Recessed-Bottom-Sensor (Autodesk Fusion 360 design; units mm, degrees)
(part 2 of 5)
sketch "M5 stop reinforcement bolt" plane through (-36.1, 0, 0) normal (1, 0, 0) x axis (0, 0, -1)
  circle C1 centre (-79.6754, -33.9652) radius 2.7
extrude "Extrude12" cut sketch "M5 stop reinforcement bolt" along normal blind 27.2
work_plane "WorkPlane13" AlongDistance -15.4 ExtraOffset 0
sketch "M5 captive stop nut" plane through (-15.4, 0, 0) normal (1, 0, 0) x axis (0, 0, -1)
  line L1 (-83.8754, -31.5403) -> (-79.6754, -29.1154)
  line L2 (-83.8754, -36.39) -> (-83.8754, -31.5403)
  line L3 (-79.6754, -38.8149) -> (-83.8754, -36.39)
  line L4 (-75.4754, -36.39) -> (-79.6754, -38.8149)
  line L5 (-75.4754, -31.5403) -> (-75.4754, -36.39)
  line L6 (-79.6754, -29.1154) -> (-75.4754, -31.5403)
extrude "Extrude13" cut sketch "M5 captive stop nut" along normal blind 6.5
work_plane "WorkPlane14" AlongDistance -36 ExtraOffset 0
sketch "Broad stop support ear (1)" plane through (-36, 0, 0) normal (1, 0, 0) x axis (0, 0, -1)
  line L1 (-60, 44) -> (-60, 20)
  line L2 (-90, 44) -> (-60, 44)
  line L3 (-90, 20) -> (-90, 44)
  line L4 (-60, 20) -> (-90, 20)
extrude "Extrude14" add sketch "Broad stop support ear (1)" along normal blind 12
work_plane "WorkPlane15" AlongDistance -24 ExtraOffset 0
sketch "Integrated steel-core end stop (1)" plane through (-24, 0, 0) normal (1, 0, 0) x axis (0, 0, -1)
  circle C1 centre (-79.6754, 33.9652) radius 6
extrude "Extrude15" add sketch "Integrated steel-core end stop (1)" along normal blind 15
work_plane "WorkPlane16" AlongDistance -36.1 ExtraOffset 0
sketch "M5 stop reinforcement bolt (1)" plane through (-36.1, 0, 0) normal (1, 0, 0) x axis (0, 0, -1)
  circle C1 centre (-79.6754, 33.9652) radius 2.7
extrude "Extrude16" cut sketch "M5 stop reinforcement bolt (1)" along normal blind 27.2
work_plane "WorkPlane17" AlongDistance -15.4 ExtraOffset 0
sketch "M5 captive stop nut (1)" plane through (-15.4, 0, 0) normal (1, 0, 0) x axis (0, 0, -1)
  line L1 (-83.8754, 36.39) -> (-79.6754, 38.8149)
  line L2 (-83.8754, 31.5403) -> (-83.8754, 36.39)
  line L3 (-79.6754, 29.1154) -> (-83.8754, 31.5403)
  line L4 (-75.4754, 31.5403) -> (-79.6754, 29.1154)
  line L5 (-75.4754, 36.39) -> (-75.4754, 31.5403)
  line L6 (-79.6754, 38.8149) -> (-75.4754, 36.39)
extrude "Extrude17" cut sketch "M5 captive stop nut (1)" along normal blind 6.5
work_plane "WorkPlane13" AlongDistance -24 ExtraOffset 0
sketch "Restore shaft socket through stop-lug root" plane through (-24, 0, 0) normal (1, 0, 0) x axis (0, 0, -1)
  line L1 (-69.6247, 6.65) -> (-60.3753, 6.65)
  arc A1 centre (-65, 0) radius 8.1 clockwise from (-60.3753, 6.65) to (-69.6247, 6.65)
extrude "Extrude13" cut sketch "Restore shaft socket through stop-lug root" along normal blind 48
work_plane "WorkPlane10" AlongDistance -24.1 ExtraOffset 0
sketch "Cam sweep clearance through crossblock" plane through (-24.1, 0, 0) normal (1, 0, 0) x axis (0, 0, -1)
  circle C1 centre (-65, 0) radius 51
extrude "Extrude10" cut sketch "Cam sweep clearance through crossblock" along normal blind 48.2
work_plane "WorkPlane10" AlongDistance 36 ExtraOffset 0
sketch "Rigid sensor carriage support" plane through (36, 0, 0) normal (1, 0, 0) x axis (0, 0, -1)
  line L1 (-49, -18) -> (-49, -28)
  line L2 (-81, -18) -> (-49, -18)
  line L3 (-81, -28) -> (-81, -18)
  line L4 (-49, -28) -> (-81, -28)
extrude "Extrude10" add sketch "Rigid sensor carriage support" along normal blind 44
work_plane "WorkPlane11" AlongDistance -28.1 ExtraOffset 0
sketch "M3 sensor carriage heat set" plane through (0, -28.1, 0) normal (0, 1, 0) x axis (1, 0, 0)
  circle C1 centre (74, -65) radius 2
extrude "Extrude11" cut sketch "M3 sensor carriage heat set" along normal blind 6.8
work_plane "WorkPlane12" AlongDistance 36 ExtraOffset 0
sketch "Rigid sensor carriage support (1)" plane through (36, 0, 0) normal (1, 0, 0) x axis (0, 0, -1)
  line L1 (-49, 28) -> (-49, 18)
  line L2 (-81, 28) -> (-49, 28)
  line L3 (-81, 18) -> (-81, 28)
  line L4 (-49, 18) -> (-81, 18)
extrude "Extrude12" add sketch "Rigid sensor carriage support (1)" along normal blind 44
work_plane "WorkPlane13" AlongDistance 21.3 ExtraOffset 0
sketch "M3 sensor carriage heat set (1)" plane through (0, 21.3, 0) normal (0, 1, 0) x axis (1, 0, 0)
  circle C1 centre (74, -65) radius 2
extrude "Extrude13" cut sketch "M3 sensor carriage heat set (1)" along normal blind 6.8
work_plane "WorkPlane1" AlongDistance -24 ExtraOffset 0
sketch "Controlled follower end float" plane through (-24, 0, 0) normal (1, 0, 0) x axis (0, 0, -1)
  circle C1 centre (-12, -35) radius 6
extrude "Extrude1" new body sketch "Controlled follower end float" along normal blind 27.8 bodies "P21 Follower left axial spacer"
work_plane "WorkPlane2" AlongDistance -24.1 ExtraOffset 0
sketch "Pivot sleeve running clearance" plane through (-24.1, 0, 0) normal (1, 0, 0) x axis (0, 0, -1)
  circle C1 centre (-12, -35) radius 4.2
extrude "Extrude2" cut sketch "Pivot sleeve running clearance" along normal blind 28
work_plane "WorkPlane1" AlongDistance 20.2 ExtraOffset 0
sketch "Controlled follower end float" plane through (20.2, 0, 0) normal (1, 0, 0) x axis (0, 0, -1)
  circle C1 centre (-12, -35) radius 6
extrude "Extrude1" new body sketch "Controlled follower end float" along normal blind 3.8 bodies "P22 Follower right axial spacer"
work_plane "WorkPlane2" AlongDistance 20.1 ExtraOffset 0
sketch "Pivot sleeve running clearance" plane through (20.1, 0, 0) normal (1, 0, 0) x axis (0, 0, -1)
  circle C1 centre (-12, -35) radius 4.2
extrude "Extrude2" cut sketch "Pivot sleeve running clearance" along normal blind 4
work_plane "WorkPlane1" AlongDistance 3.1 ExtraOffset 0
sketch "Roller axle M3 nut" plane through (3.1, 0, 0) normal (1, 0, 0) x axis (0, 0, -1)
  line L1 (-14.75, 1.5877) -> (-12, 3.1754)
  line L2 (-14.75, -1.5877) -> (-14.75, 1.5877)
  line L3 (-12, -3.1754) -> (-14.75, -1.5877)
  line L4 (-9.25, -1.5877) -> (-12, -3.1754)
  line L5 (-9.25, 1.5877) -> (-9.25, -1.5877)
  line L6 (-12, 3.1754) -> (-9.25, 1.5877)
extrude "Extrude1" new body sketch "Roller axle M3 nut" along normal blind 2.4 bodies "HARDWARE Roller axle M3 nut"
work_plane "WorkPlane2" AlongDistance 3 ExtraOffset 0
sketch "Thread envelope" plane through (3, 0, 0) normal (1, 0, 0) x axis (0, 0, -1)
  circle C1 centre (-12, 0) radius 1.5
extrude "Extrude2" cut sketch "Thread envelope" along normal blind 2.6
work_plane "WorkPlane14" AlongDistance 23.9 ExtraOffset 0
sketch "Cam lateral service opening" plane through (23.9, 0, 0) normal (1, 0, 0) x axis (0, 0, -1)
  line L1 (-42.2047, 46.7373) -> (-43.8497, 47.5044)
  line L2 (-40.5875, 45.9133) -> (-42.2047, 46.7373)
  line L3 (-39, 45.0333) -> (-40.5875, 45.9133)
  line L4 (-37.4442, 44.0985) -> (-39, 45.0333)
  line L5 (-35.922, 43.11) -> (-37.4442, 44.0985)
  line L6 (-34.4352, 42.0689) -> (-35.922, 43.11)
  line L7 (-32.9856, 40.9766) -> (-34.4352, 42.0689)
  line L8 (-31.575, 39.8343) -> (-32.9856, 40.9766)
  line L9 (-30.2052, 38.6435) -> (-31.575, 39.8343)
  line L10 (-28.8778, 37.4057) -> (-30.2052, 38.6435)
  line L11 (-27.5943, 36.1222) -> (-28.8778, 37.4057)
  line L12 (-26.3565, 34.7948) -> (-27.5943, 36.1222)
  line L13 (-25.1657, 33.425) -> (-26.3565, 34.7948)
  line L14 (-24.0234, 32.0144) -> (-25.1657, 33.425)
  line L15 (-22.9311, 30.5648) -> (-24.0234, 32.0144)
  line L16 (-21.89, 29.078) -> (-22.9311, 30.5648)
  line L17 (-20.9015, 27.5558) -> (-21.89, 29.078)
  line L18 (-19.9667, 26) -> (-20.9015, 27.5558)
  line L19 (-19.0867, 24.4125) -> (-19.9667, 26)
  line L20 (-18.2627, 22.7953) -> (-19.0867, 24.4125)
  line L21 (-17.4956, 21.1503) -> (-18.2627, 22.7953)
  line L22 (-16.7864, 19.4795) -> (-17.4956, 21.1503)
  line L23 (-16.136, 17.785) -> (-16.7864, 19.4795)
  line L24 (-15.5451, 16.0689) -> (-16.136, 17.785)
  line L25 (-15.0144, 14.3331) -> (-15.5451, 16.0689)
  line L26 (-14.5446, 12.5799) -> (-15.0144, 14.3331)
  line L27 (-14.1363, 10.8114) -> (-14.5446, 12.5799)
  line L28 (-13.79, 9.0297) -> (-14.1363, 10.8114)
  line L29 (-13.5061, 7.237) -> (-13.79, 9.0297)
  line L30 (-13.2849, 5.4355) -> (-13.5061, 7.237)
  line L31 (-13.1267, 3.6273) -> (-13.2849, 5.4355)
  line L32 (-13.0317, 1.8148) -> (-13.1267, 3.6273)
  line L33 (-13, 0) -> (-13.0317, 1.8148)
  line L34 (-13.0317, -1.8148) -> (-13, 0)
  line L35 (-13.1267, -3.6273) -> (-13.0317, -1.8148)
  line L36 (-13.2849, -5.4355) -> (-13.1267, -3.6273)
  line L37 (-13.5061, -7.237) -> (-13.2849, -5.4355)
  line L38 (-13.79, -9.0297) -> (-13.5061, -7.237)
  line L39 (-14.1363, -10.8114) -> (-13.79, -9.0297)
  line L40 (-14.5446, -12.5799) -> (-14.1363, -10.8114)
  line L41 (-15.0144, -14.3331) -> (-14.5446, -12.5799)
  line L42 (-15.5451, -16.0689) -> (-15.0144, -14.3331)
  line L43 (-16.136, -17.785) -> (-15.5451, -16.0689)
  line L44 (-16.7864, -19.4795) -> (-16.136, -17.785)
  line L45 (-17.4956, -21.1503) -> (-16.7864, -19.4795)
  line L46 (-18.2627, -22.7953) -> (-17.4956, -21.1503)
  line L47 (-19.0867, -24.4125) -> (-18.2627, -22.7953)
  line L48 (-19.9667, -26) -> (-19.0867, -24.4125)
  line L49 (-20.9015, -27.5558) -> (-19.9667, -26)
  line L50 (-21.89, -29.078) -> (-20.9015, -27.5558)
  line L51 (-22.9311, -30.5648) -> (-21.89, -29.078)
  line L52 (-24.0234, -32.0144) -> (-22.9311, -30.5648)
  line L53 (-25.1657, -33.425) -> (-24.0234, -32.0144)
  line L54 (-26.3565, -34.7948) -> (-25.1657, -33.425)
  line L55 (-27.5943, -36.1222) -> (-26.3565, -34.7948)
  line L56 (-28.8778, -37.4057) -> (-27.5943, -36.1222)
  line L57 (-30.2052, -38.6435) -> (-28.8778, -37.4057)
  line L58 (-31.575, -39.8343) -> (-30.2052, -38.6435)
  line L59 (-32.9856, -40.9766) -> (-31.575, -39.8343)
  line L60 (-34.4352, -42.0689) -> (-32.9856, -40.9766)
  line L61 (-35.922, -43.11) -> (-34.4352, -42.0689)
  line L62 (-37.4442, -44.0985) -> (-35.922, -43.11)
  line L63 (-39, -45.0333) -> (-37.4442, -44.0985)
  line L64 (-40.5875, -45.9133) -> (-39, -45.0333)
  line L65 (-42.2047, -46.7373) -> (-40.5875, -45.9133)
  line L66 (-43.8497, -47.5044) -> (-42.2047, -46.7373)
  line L67 (-54.4248, -23.7522) -> (-43.8497, -47.5044)
  line L68 (-53.6024, -23.3686) -> (-54.4248, -23.7522)
  line L69 (-52.7937, -22.9566) -> (-53.6024, -23.3686)
  line L70 (-52, -22.5167) -> (-52.7937, -22.9566)
  line L71 (-51.2221, -22.0493) -> (-52, -22.5167)
  line L72 (-50.461, -21.555) -> (-51.2221, -22.0493)
  line L73 (-49.7176, -21.0344) -> (-50.461, -21.555)
  line L74 (-48.9928, -20.4883) -> (-49.7176, -21.0344)
  line L75 (-48.2875, -19.9172) -> (-48.9928, -20.4883)
  line L76 (-47.6026, -19.3218) -> (-48.2875, -19.9172)
  line L77 (-46.9389, -18.7028) -> (-47.6026, -19.3218)
  line L78 (-46.2972, -18.0611) -> (-46.9389, -18.7028)
  line L79 (-45.6782, -17.3974) -> (-46.2972, -18.0611)
  line L80 (-45.0828, -16.7125) -> (-45.6782, -17.3974)
  line L81 (-44.5117, -16.0072) -> (-45.0828, -16.7125)
  line L82 (-43.9656, -15.2824) -> (-44.5117, -16.0072)
  line L83 (-43.445, -14.539) -> (-43.9656, -15.2824)
  line L84 (-42.9507, -13.7779) -> (-43.445, -14.539)
  line L85 (-42.4833, -13) -> (-42.9507, -13.7779)
  line L86 (-42.0434, -12.2063) -> (-42.4833, -13)
  line L87 (-41.6314, -11.3976) -> (-42.0434, -12.2063)
  line L88 (-41.2478, -10.5752) -> (-41.6314, -11.3976)
  line L89 (-40.8932, -9.7398) -> (-41.2478, -10.5752)
  line L90 (-40.568, -8.8925) -> (-40.8932, -9.7398)
  line L91 (-40.2725, -8.0344) -> (-40.568, -8.8925)
  line L92 (-40.0072, -7.1666) -> (-40.2725, -8.0344)
  line L93 (-39.7723, -6.29) -> (-40.0072, -7.1666)
  line L94 (-39.5682, -5.4057) -> (-39.7723, -6.29)
  line L95 (-39.395, -4.5149) -> (-39.5682, -5.4057)
  line L96 (-39.253, -3.6185) -> (-39.395, -4.5149)
  line L97 (-39.1424, -2.7177) -> (-39.253, -3.6185)
  line L98 (-39.0633, -1.8137) -> (-39.1424, -2.7177)
  line L99 (-39.0158, -0.9074) -> (-39.0633, -1.8137)
  line L100 (-39, 0) -> (-39.0158, -0.9074)
  line L101 (-39.0158, 0.9074) -> (-39, 0)
  line L102 (-39.0633, 1.8137) -> (-39.0158, 0.9074)
  line L103 (-39.1424, 2.7177) -> (-39.0633, 1.8137)
  line L104 (-39.253, 3.6185) -> (-39.1424, 2.7177)
  line L105 (-39.395, 4.5149) -> (-39.253, 3.6185)
  line L106 (-39.5682, 5.4057) -> (-39.395, 4.5149)
  line L107 (-39.7723, 6.29) -> (-39.5682, 5.4057)
  line L108 (-40.0072, 7.1666) -> (-39.7723, 6.29)
  line L109 (-40.2725, 8.0344) -> (-40.0072, 7.1666)
  line L110 (-40.568, 8.8925) -> (-40.2725, 8.0344)
  line L111 (-40.8932, 9.7398) -> (-40.568, 8.8925)
  line L112 (-41.2478, 10.5752) -> (-40.8932, 9.7398)
  line L113 (-41.6314, 11.3976) -> (-41.2478, 10.5752)
  line L114 (-42.0434, 12.2063) -> (-41.6314, 11.3976)
  line L115 (-42.4833, 13) -> (-42.0434, 12.2063)
  line L116 (-42.9507, 13.7779) -> (-42.4833, 13)
  line L117 (-43.445, 14.539) -> (-42.9507, 13.7779)
  line L118 (-43.9656, 15.2824) -> (-43.445, 14.539)
  line L119 (-44.5117, 16.0072) -> (-43.9656, 15.2824)
  line L120 (-45.0828, 16.7125) -> (-44.5117, 16.0072)
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extrude "Extrude14" cut sketch "Cam lateral service opening" along normal blind 12.2
work_plane "WorkPlane15" AlongDistance 36 ExtraOffset 0
sketch "Clear service path beneath sensor rails" plane through (36, 0, 0) normal (1, 0, 0) x axis (0, 0, -1)
  line L1 (-48.9, -18) -> (-48.9, -28)
  line L2 (-56, -18) -> (-48.9, -18)
  line L3 (-56, -28) -> (-56, -18)
  line L4 (-48.9, -28) -> (-56, -28)
extrude "Extrude15" cut sketch "Clear service path beneath sensor rails" along normal blind 44.1
work_plane "WorkPlane16" AlongDistance 36 ExtraOffset 0
sketch "Clear service path beneath sensor rails (1)" plane through (36, 0, 0) normal (1, 0, 0) x axis (0, 0, -1)
  line L1 (-48.9, 28) -> (-48.9, 18)
  line L2 (-56, 28) -> (-48.9, 28)
  line L3 (-56, 18) -> (-56, 28)
  line L4 (-48.9, 18) -> (-56, 18)
extrude "Extrude16" cut sketch "Clear service path beneath sensor rails (1)" along normal blind 44.1
work_plane "WorkPlane11" AlongDistance -24 ExtraOffset 0
sketch "Raise mount clear of rail bolt axes" plane through (-24, 0, 0) normal (1, 0, 0) x axis (0, 0, -1)
  line L1 (-52, -44) -> (-52, -66)
  line L2 (-57, -44) -> (-52, -44)
  line L3 (-57, -66) -> (-57, -44)
  line L4 (-52, -66) -> (-57, -66)
extrude "Extrude11" add sketch "Raise mount clear of rail bolt axes" along normal blind 48
work_plane "WorkPlane12" AlongDistance -24 ExtraOffset 0
sketch "Close old block mounting hole" plane through (-24, 0, 0) normal (1, 0, 0) x axis (0, 0, -1)
  circle C1 centre (-44, -59) radius 2.01
extrude "Extrude12" add sketch "Close old block mounting hole" along normal blind 8.7
work_plane "WorkPlane13" AlongDistance -24.1 ExtraOffset 0
sketch "Raised M3 block insert" plane through (-24.1, 0, 0) normal (1, 0, 0) x axis (0, 0, -1)
  circle C1 centre (-52, -59) radius 2
extrude "Extrude13" cut sketch "Raised M3 block insert" along normal blind 8.9
work_plane "WorkPlane14" AlongDistance 15.3 ExtraOffset 0
sketch "Close old block mounting hole (1)" plane through (15.3, 0, 0) normal (1, 0, 0) x axis (0, 0, -1)
  circle C1 centre (-44, -59) radius 2.01
extrude "Extrude14" add sketch "Close old block mounting hole (1)" along normal blind 8.7
work_plane "WorkPlane15" AlongDistance 15.2 ExtraOffset 0
sketch "Raised M3 block insert (1)" plane through (15.2, 0, 0) normal (1, 0, 0) x axis (0, 0, -1)
  circle C1 centre (-52, -59) radius 2
extrude "Extrude15" cut sketch "Raised M3 block insert (1)" along normal blind 8.9
work_plane "WorkPlane18" AlongDistance -36 ExtraOffset 0
sketch "Close old plate mounting hole" plane through (-36, 0, 0) normal (1, 0, 0) x axis (0, 0, -1)
  circle C1 centre (-44, -59) radius 1.71
extrude "Extrude18" add sketch "Close old plate mounting hole" along normal blind 12
work_plane "WorkPlane19" AlongDistance -36.1 ExtraOffset 0
sketch "Raised M3 block fastener" plane through (-36.1, 0, 0) normal (1, 0, 0) x axis (0, 0, -1)
  circle C1 centre (-52, -59) radius 1.7
extrude "Extrude19" cut sketch "Raised M3 block fastener" along normal blind 12.2
work_plane "WorkPlane17" AlongDistance 24 ExtraOffset 0
sketch "Close old plate mounting hole" plane through (24, 0, 0) normal (1, 0, 0) x axis (0, 0, -1)
  circle C1 centre (-44, -59) radius 1.71
extrude "Extrude17" add sketch "Close old plate mounting hole" along normal blind 12
work_plane "WorkPlane18" AlongDistance 23.9 ExtraOffset 0
sketch "Raised M3 block fastener" plane through (23.9, 0, 0) normal (1, 0, 0) x axis (0, 0, -1)
  circle C1 centre (-52, -59) radius 1.7
extrude "Extrude18" cut sketch "Raised M3 block fastener" along normal blind 12.2
work_plane "WorkPlane16" AlongDistance -24 ExtraOffset 0
sketch "Close old block mounting hole (2)" plane through (-24, 0, 0) normal (1, 0, 0) x axis (0, 0, -1)
  circle C1 centre (-44, -51) radius 2.01
extrude "Extrude16" add sketch "Close old block mounting hole (2)" along normal blind 8.7
work_plane "WorkPlane17" AlongDistance -24.1 ExtraOffset 0
sketch "Raised M3 block insert (2)" plane through (-24.1, 0, 0) normal (1, 0, 0) x axis (0, 0, -1)
  circle C1 centre (-52, -51) radius 2
extrude "Extrude17" cut sketch "Raised M3 block insert (2)" along normal blind 8.9
work_plane "WorkPlane18" AlongDistance 15.3 ExtraOffset 0
sketch "Close old block mounting hole (3)" plane through (15.3, 0, 0) normal (1, 0, 0) x axis (0, 0, -1)
  circle C1 centre (-44, -51) radius 2.01
extrude "Extrude18" add sketch "Close old block mounting hole (3)" along normal blind 8.7
work_plane "WorkPlane19" AlongDistance 15.2 ExtraOffset 0
sketch "Raised M3 block insert (3)" plane through (15.2, 0, 0) normal (1, 0, 0) x axis (0, 0, -1)
  circle C1 centre (-52, -51) radius 2
extrude "Extrude19" cut sketch "Raised M3 block insert (3)" along normal blind 8.9
work_plane "WorkPlane20" AlongDistance -36 ExtraOffset 0
sketch "Close old plate mounting hole (1)" plane through (-36, 0, 0) normal (1, 0, 0) x axis (0, 0, -1)
  circle C1 centre (-44, -51) radius 1.71
extrude "Extrude20" add sketch "Close old plate mounting hole (1)" along normal blind 12
work_plane "WorkPlane21" AlongDistance -36.1 ExtraOffset 0
sketch "Raised M3 block fastener (1)" plane through (-36.1, 0, 0) normal (1, 0, 0) x axis (0, 0, -1)
  circle C1 centre (-52, -51) radius 1.7
extrude "Extrude21" cut sketch "Raised M3 block fastener (1)" along normal blind 12.2
work_plane "WorkPlane19" AlongDistance 24 ExtraOffset 0
sketch "Close old plate mounting hole (1)" plane through (24, 0, 0) normal (1, 0, 0) x axis (0, 0, -1)
  circle C1 centre (-44, -51) radius 1.71
extrude "Extrude19" add sketch "Close old plate mounting hole (1)" along normal blind 12
work_plane "WorkPlane20" AlongDistance 23.9 ExtraOffset 0
sketch "Raised M3 block fastener (1)" plane through (23.9, 0, 0) normal (1, 0, 0) x axis (0, 0, -1)
  circle C1 centre (-52, -51) radius 1.7
extrude "Extrude20" cut sketch "Raised M3 block fastener (1)" along normal blind 12.2
work_plane "WorkPlane20" AlongDistance 51.9 ExtraOffset 0
sketch "Continue adjuster bore" plane through (0, 0, 51.9) normal (0, 0, 1) x axis (1, 0, 0)
  circle C1 centre (12, -55) radius 2.2
extrude "Extrude20" cut sketch "Continue adjuster bore" along normal blind 5.2
work_plane "WorkPlane21" AlongDistance 51.9 ExtraOffset 0
sketch "Continue guide bore" plane through (0, 0, 51.9) normal (0, 0, 1) x axis (1, 0, 0)
  circle C1 centre (5, -55) radius 1.7
extrude "Extrude21" cut sketch "Continue guide bore" along normal blind 5.2
work_plane "WorkPlane22" AlongDistance 51.9 ExtraOffset 0
sketch "Continue guide bore (1)" plane through (0, 0, 51.9) normal (0, 0, 1) x axis (1, 0, 0)
  circle C1 centre (19, -55) radius 1.7
extrude "Extrude22" cut sketch "Continue guide bore (1)" along normal blind 5.2
work_plane "WorkPlane23" AlongDistance -24.1 ExtraOffset 0
sketch "Preserve cam sweep clearance" plane through (-24.1, 0, 0) normal (1, 0, 0) x axis (0, 0, -1)
  circle C1 centre (-65, 0) radius 51
extrude "Extrude23" cut sketch "Preserve cam sweep clearance" along normal blind 48.2
work_plane "WorkPlane1" AlongDistance -23.85 ExtraOffset 0
sketch "Controlled rotor axial clearance" plane through (-23.85, 0, 0) normal (1, 0, 0) x axis (0, 0, -1)
  circle C1 centre (-65, 0) radius 10
extrude "Extrude1" new body sketch "Controlled rotor axial clearance" along normal blind 16.85 bodies "P23 Left rotor thrust spacer"
work_plane "WorkPlane2" AlongDistance -23.95 ExtraOffset 0
sketch "Free spacer bore" plane through (-23.95, 0, 0) normal (1, 0, 0) x axis (0, 0, -1)
  circle C1 centre (-65, 0) radius 8.2
extrude "Extrude2" cut sketch "Free spacer bore" along normal blind 17.05
work_plane "WorkPlane1" AlongDistance 7 ExtraOffset 0
sketch "Controlled rotor axial clearance" plane through (7, 0, 0) normal (1, 0, 0) x axis (0, 0, -1)
  circle C1 centre (-65, 0) radius 10
extrude "Extrude1" new body sketch "Controlled rotor axial clearance" along normal blind 16.85 bodies "P24 Right rotor thrust spacer"
work_plane "WorkPlane2" AlongDistance 6.9 ExtraOffset 0
sketch "Free spacer bore" plane through (6.9, 0, 0) normal (1, 0, 0) x axis (0, 0, -1)
  circle C1 centre (-65, 0) radius 8.2
extrude "Extrude2" cut sketch "Free spacer bore" along normal blind 17.05
work_plane "WorkPlane22" AlongDistance -76 ExtraOffset 0
sketch "Restore rail bolt clearance after hole filling" plane through (0, -76, 0) normal (0, 1, 0) x axis (1, 0, 0)
  circle C1 centre (-30, -45) radius 2.7
extrude "Extrude22" cut sketch "Restore rail bolt clearance after hole filling" along normal blind 22
work_plane "WorkPlane23" AlongDistance 54 ExtraOffset 0
sketch "Restore rail bolt clearance after hole filling (1)" plane through (0, 54, 0) normal (0, 1, 0) x axis (1, 0, 0)
  circle C1 centre (-30, -45) radius 2.7
work_plane "WorkPlane24" AlongDistance -55 ExtraOffset 0
sketch "Restore rail head access after hole filling" plane through (0, -55, 0) normal (0, 1, 0) x axis (1, 0, 0)
  circle C1 centre (-30, -45) radius 5.3
extrude "Extrude24" cut sketch "Restore rail head access after hole filling" along normal blind 12
work_plane "WorkPlane25" AlongDistance 43 ExtraOffset 0
sketch "Restore rail head access after hole filling (1)" plane through (0, 43, 0) normal (0, 1, 0) x axis (1, 0, 0)
  circle C1 centre (-30, -45) radius 5.3
work_plane "WorkPlane21" AlongDistance -76 ExtraOffset 0
sketch "Restore rail bolt clearance after hole filling" plane through (0, -76, 0) normal (0, 1, 0) x axis (1, 0, 0)
  circle C1 centre (30, -45) radius 2.7
extrude "Extrude21" cut sketch "Restore rail bolt clearance after hole filling" along normal blind 22
work_plane "WorkPlane22" AlongDistance 54 ExtraOffset 0
sketch "Restore rail bolt clearance after hole filling (1)" plane through (0, 54, 0) normal (0, 1, 0) x axis (1, 0, 0)
  circle C1 centre (30, -45) radius 2.7
work_plane "WorkPlane23" AlongDistance -55 ExtraOffset 0
sketch "Restore rail head access after hole filling" plane through (0, -55, 0) normal (0, 1, 0) x axis (1, 0, 0)
  circle C1 centre (30, -45) radius 5.3
extrude "Extrude23" cut sketch "Restore rail head access after hole filling" along normal blind 12
work_plane "WorkPlane24" AlongDistance 43 ExtraOffset 0
sketch "Restore rail head access after hole filling (1)" plane through (0, 43, 0) normal (0, 1, 0) x axis (1, 0, 0)
  circle C1 centre (30, -45) radius 5.3
work_plane "WorkPlane14" AlongDistance -18.1 ExtraOffset 0
sketch "Stop lug clearance for concentric thrust spacer" plane through (-18.1, 0, 0) normal (1, 0, 0) x axis (0, 0, -1)
  circle C1 centre (-65, 0) radius 10.2
extrude "Extrude14" cut sketch "Stop lug clearance for concentric thrust spacer" along normal blind 11
work_plane "WorkPlane15" AlongDistance -18.1 ExtraOffset 0
sketch "Complete stop lug relief to rotor face" plane through (-18.1, 0, 0) normal (1, 0, 0) x axis (0, 0, -1)
  circle C1 centre (-65, 0) radius 10.2
extrude "Extrude15" cut sketch "Complete stop lug relief to rotor face" along normal blind 11.1
ground "Pin2"
ground "Pin3"
ground "Pin4"
ground "Pin5"
ground "Pin6"
ground "Pin11"
ground "Pin12"
ground "Pin48"
ground "Pin49"
work_plane "WorkPlane24" AlongDistance -24 ExtraOffset 0
sketch "Extra roof over relocated heat-set inserts" plane through (-24, 0, 0) normal (1, 0, 0) x axis (0, 0, -1)
  line L1 (-57, -44) -> (-57, -66)
  line L2 (-59, -44) -> (-57, -44)
  line L3 (-59, -66) -> (-59, -44)
  line L4 (-57, -66) -> (-59, -66)
extrude "Extrude24" add sketch "Extra roof over relocated heat-set inserts" along normal blind 48
work_plane "WorkPlane25" AlongDistance -24 ExtraOffset 0
sketch "Fill former insert location" plane through (-24, 0, 0) normal (1, 0, 0) x axis (0, 0, -1)
  circle C1 centre (-52, -59) radius 2.01
extrude "Extrude25" add sketch "Fill former insert location" along normal blind 8.7
work_plane "WorkPlane26" AlongDistance 15.3 ExtraOffset 0
sketch "Fill former insert location (1)" plane through (15.3, 0, 0) normal (1, 0, 0) x axis (0, 0, -1)
  circle C1 centre (-52, -59) radius 2.01
extrude "Extrude26" add sketch "Fill former insert location (1)" along normal blind 8.7
work_plane "WorkPlane26" AlongDistance -36 ExtraOffset 0
sketch "Fill former plate mounting hole" plane through (-36, 0, 0) normal (1, 0, 0) x axis (0, 0, -1)
  circle C1 centre (-52, -59) radius 1.71
extrude "Extrude26" add sketch "Fill former plate mounting hole" along normal blind 12
work_plane "WorkPlane25" AlongDistance 24 ExtraOffset 0
sketch "Fill former plate mounting hole" plane through (24, 0, 0) normal (1, 0, 0) x axis (0, 0, -1)
  circle C1 centre (-52, -59) radius 1.71
extrude "Extrude25" add sketch "Fill former plate mounting hole" along normal blind 12
work_plane "WorkPlane27" AlongDistance -24 ExtraOffset 0
sketch "Fill former insert location (2)" plane through (-24, 0, 0) normal (1, 0, 0) x axis (0, 0, -1)
  circle C1 centre (-52, -51) radius 2.01
extrude "Extrude27" add sketch "Fill former insert location (2)" along normal blind 8.7
work_plane "WorkPlane28" AlongDistance 15.3 ExtraOffset 0
sketch "Fill former insert location (3)" plane through (15.3, 0, 0) normal (1, 0, 0) x axis (0, 0, -1)
  circle C1 centre (-52, -51) radius 2.01
extrude "Extrude28" add sketch "Fill former insert location (3)" along normal blind 8.7
work_plane "WorkPlane27" AlongDistance -36 ExtraOffset 0
sketch "Fill former plate mounting hole (1)" plane through (-36, 0, 0) normal (1, 0, 0) x axis (0, 0, -1)
  circle C1 centre (-52, -51) radius 1.71
extrude "Extrude27" add sketch "Fill former plate mounting hole (1)" along normal blind 12
work_plane "WorkPlane26" AlongDistance 24 ExtraOffset 0
sketch "Fill former plate mounting hole (1)" plane through (24, 0, 0) normal (1, 0, 0) x axis (0, 0, -1)
  circle C1 centre (-52, -51) radius 1.71
extrude "Extrude26" add sketch "Fill former plate mounting hole (1)" along normal blind 12
work_plane "WorkPlane29" AlongDistance -24.1 ExtraOffset 0
sketch "Relocated insert with cam-side retaining wall" plane through (-24.1, 0, 0) normal (1, 0, 0) x axis (0, 0, -1)
  circle C1 centre (-53.5, -62) radius 2
extrude "Extrude29" cut sketch "Relocated insert with cam-side retaining wall" along normal blind 8.9
work_plane "WorkPlane30" AlongDistance 15.3 ExtraOffset 0
sketch "Relocated insert with cam-side retaining wall (1)" plane through (15.3, 0, 0) normal (1, 0, 0) x axis (0, 0, -1)
  circle C1 centre (-53.5, -62) radius 2
extrude "Extrude30" cut sketch "Relocated insert with cam-side retaining wall (1)" along normal blind 8.9
work_plane "WorkPlane28" AlongDistance -36.1 ExtraOffset 0
sketch "Relocated mount above rail counterbore" plane through (-36.1, 0, 0) normal (1, 0, 0) x axis (0, 0, -1)
  circle C1 centre (-53.5, -62) radius 1.7
extrude "Extrude28" cut sketch "Relocated mount above rail counterbore" along normal blind 12.2
work_plane "WorkPlane27" AlongDistance 23.9 ExtraOffset 0
sketch "Relocated mount above rail counterbore" plane through (23.9, 0, 0) normal (1, 0, 0) x axis (0, 0, -1)
  circle C1 centre (-53.5, -62) radius 1.7
extrude "Extrude27" cut sketch "Relocated mount above rail counterbore" along normal blind 12.2
work_plane "WorkPlane31" AlongDistance -24.1 ExtraOffset 0
sketch "Relocated insert with cam-side retaining wall (2)" plane through (-24.1, 0, 0) normal (1, 0, 0) x axis (0, 0, -1)
  circle C1 centre (-53.5, -54) radius 2
extrude "Extrude31" cut sketch "Relocated insert with cam-side retaining wall (2)" along normal blind 8.9
work_plane "WorkPlane32" AlongDistance 15.3 ExtraOffset 0
sketch "Relocated insert with cam-side retaining wall (3)" plane through (15.3, 0, 0) normal (1, 0, 0) x axis (0, 0, -1)
  circle C1 centre (-53.5, -54) radius 2
extrude "Extrude32" cut sketch "Relocated insert with cam-side retaining wall (3)" along normal blind 8.9
work_plane "WorkPlane29" AlongDistance -36.1 ExtraOffset 0
sketch "Relocated mount above rail counterbore (1)" plane through (-36.1, 0, 0) normal (1, 0, 0) x axis (0, 0, -1)
  circle C1 centre (-53.5, -54) radius 1.7
extrude "Extrude29" cut sketch "Relocated mount above rail counterbore (1)" along normal blind 12.2
work_plane "WorkPlane28" AlongDistance 23.9 ExtraOffset 0
sketch "Relocated mount above rail counterbore (1)" plane through (23.9, 0, 0) normal (1, 0, 0) x axis (0, 0, -1)
  circle C1 centre (-53.5, -54) radius 1.7
extrude "Extrude28" cut sketch "Relocated mount above rail counterbore (1)" along normal blind 12.2
work_plane "WorkPlane33" AlongDistance 51.9 ExtraOffset 0
sketch "Continue adjuster bore through roof" plane through (0, 0, 51.9) normal (0, 0, 1) x axis (1, 0, 0)
  circle C1 centre (12, -55) radius 2.2
extrude "Extrude33" cut sketch "Continue adjuster bore through roof" along normal blind 7.2
work_plane "WorkPlane34" AlongDistance 51.9 ExtraOffset 0
sketch "Continue guide bore through roof" plane through (0, 0, 51.9) normal (0, 0, 1) x axis (1, 0, 0)
  circle C1 centre (5, -55) radius 1.7
extrude "Extrude34" cut sketch "Continue guide bore through roof" along normal blind 7.2
work_plane "WorkPlane35" AlongDistance 51.9 ExtraOffset 0
sketch "Continue guide bore through roof (1)" plane through (0, 0, 51.9) normal (0, 0, 1) x axis (1, 0, 0)
  circle C1 centre (19, -55) radius 1.7
extrude "Extrude35" cut sketch "Continue guide bore through roof (1)" along normal blind 7.2
work_plane "WorkPlane36" AlongDistance -24.1 ExtraOffset 0
sketch "Restore cam envelope after pocket repair" plane through (-24.1, 0, 0) normal (1, 0, 0) x axis (0, 0, -1)
  circle C1 centre (-65, 0) radius 51
extrude "Extrude36" cut sketch "Restore cam envelope after pocket repair" along normal blind 48.2
work_plane "WorkPlane30" AlongDistance -76 ExtraOffset 0
sketch "Preserve rail shank passage" plane through (0, -76, 0) normal (0, 1, 0) x axis (1, 0, 0)
  circle C1 centre (-30, -45) radius 2.7
work_plane "WorkPlane31" AlongDistance 54 ExtraOffset 0
sketch "Preserve rail shank passage (1)" plane through (0, 54, 0) normal (0, 1, 0) x axis (1, 0, 0)
  circle C1 centre (-30, -45) radius 2.7
work_plane "WorkPlane32" AlongDistance -55 ExtraOffset 0
sketch "Preserve rail head passage" plane through (0, -55, 0) normal (0, 1, 0) x axis (1, 0, 0)
  circle C1 centre (-30, -45) radius 5.3
extrude "Extrude32" cut sketch "Preserve rail head passage" along normal blind 12
work_plane "WorkPlane33" AlongDistance 43 ExtraOffset 0
sketch "Preserve rail head passage (1)" plane through (0, 43, 0) normal (0, 1, 0) x axis (1, 0, 0)
  circle C1 centre (-30, -45) radius 5.3
work_plane "WorkPlane29" AlongDistance -76 ExtraOffset 0
sketch "Preserve rail shank passage" plane through (0, -76, 0) normal (0, 1, 0) x axis (1, 0, 0)
  circle C1 centre (30, -45) radius 2.7
work_plane "WorkPlane30" AlongDistance 54 ExtraOffset 0
sketch "Preserve rail shank passage (1)" plane through (0, 54, 0) normal (0, 1, 0) x axis (1, 0, 0)
  circle C1 centre (30, -45) radius 2.7
work_plane "WorkPlane31" AlongDistance -55 ExtraOffset 0
sketch "Preserve rail head passage" plane through (0, -55, 0) normal (0, 1, 0) x axis (1, 0, 0)
  circle C1 centre (30, -45) radius 5.3
extrude "Extrude31" cut sketch "Preserve rail head passage" along normal blind 12
work_plane "WorkPlane32" AlongDistance 43 ExtraOffset 0
sketch "Preserve rail head passage (1)" plane through (0, 43, 0) normal (0, 1, 0) x axis (1, 0, 0)
  circle C1 centre (30, -45) radius 5.3
work_plane "WorkPlane16" AlongDistance -5 ExtraOffset 0
sketch "Flat washer seat for sensor-drive shaft clamp" plane through (-5, 0, 0) normal (1, 0, 0) x axis (0, 0, -1)
  line L1 (-60, 22) -> (-60, 20)
  line L2 (-70, 22) -> (-60, 22)
  line L3 (-70, 20) -> (-70, 22)
  line L4 (-60, 20) -> (-70, 20)
extrude "Extrude16" add sketch "Flat washer seat for sensor-drive shaft clamp" along normal blind 10
work_plane "WorkPlane17" AlongDistance 6.4 ExtraOffset 0
sketch "Radial screw onto printed shaft D flat" plane through (0, 6.4, 0) normal (0, 1, 0) x axis (1, 0, 0)
  circle C1 centre (0, -65) radius 1.7
extrude "Extrude17" cut sketch "Radial screw onto printed shaft D flat" along normal blind 15.7
work_plane "WorkPlane18" AlongDistance 15.2 ExtraOffset 0
sketch "M3 heatset pocket for rotor clamp" plane through (0, 15.2, 0) normal (0, 1, 0) x axis (1, 0, 0)
  circle C1 centre (0, -65) radius 2
extrude "Extrude18" cut sketch "M3 heatset pocket for rotor clamp" along normal blind 6.9
work_plane "WorkPlane37" AlongDistance -24 ExtraOffset 0
sketch "Extend reaction block into free rail bay" plane through (-24, 0, 0) normal (1, 0, 0) x axis (0, 0, -1)
  line L1 (-38, -66) -> (-38, -74)
  line L2 (-59, -66) -> (-38, -66)
  line L3 (-59, -74) -> (-59, -66)
  line L4 (-38, -74) -> (-59, -74)
extrude "Extrude37" add sketch "Extend reaction block into free rail bay" along normal blind 48
work_plane "WorkPlane38" AlongDistance -24 ExtraOffset 0
sketch "Close mounting bore that crossed cup guide" plane through (-24, 0, 0) normal (1, 0, 0) x axis (0, 0, -1)
  circle C1 centre (-53.5, -54) radius 2.01
extrude "Extrude38" add sketch "Close mounting bore that crossed cup guide" along normal blind 8.7
work_plane "WorkPlane39" AlongDistance -24.1 ExtraOffset 0
sketch "Outer mounting row clear of guide" plane through (-24.1, 0, 0) normal (1, 0, 0) x axis (0, 0, -1)
  circle C1 centre (-53.5, -70) radius 2
extrude "Extrude39" cut sketch "Outer mounting row clear of guide" along normal blind 8.9
work_plane "WorkPlane40" AlongDistance 15.3 ExtraOffset 0
sketch "Close mounting bore that crossed cup guide (1)" plane through (15.3, 0, 0) normal (1, 0, 0) x axis (0, 0, -1)
  circle C1 centre (-53.5, -54) radius 2.01
extrude "Extrude40" add sketch "Close mounting bore that crossed cup guide (1)" along normal blind 8.7
work_plane "WorkPlane41" AlongDistance 15.2 ExtraOffset 0
sketch "Outer mounting row clear of guide (1)" plane through (15.2, 0, 0) normal (1, 0, 0) x axis (0, 0, -1)
  circle C1 centre (-53.5, -70) radius 2
extrude "Extrude41" cut sketch "Outer mounting row clear of guide (1)" along normal blind 8.9
work_plane "WorkPlane34" AlongDistance -36 ExtraOffset 0
sketch "Close former inner mounting hole" plane through (-36, 0, 0) normal (1, 0, 0) x axis (0, 0, -1)
  circle C1 centre (-53.5, -54) radius 1.71
extrude "Extrude34" add sketch "Close former inner mounting hole" along normal blind 12
work_plane "WorkPlane35" AlongDistance -36.1 ExtraOffset 0
sketch "Matched outer mounting row" plane through (-36.1, 0, 0) normal (1, 0, 0) x axis (0, 0, -1)
  circle C1 centre (-53.5, -70) radius 1.7
extrude "Extrude35" cut sketch "Matched outer mounting row" along normal blind 12.2
work_plane "WorkPlane33" AlongDistance 24 ExtraOffset 0
sketch "Close former inner mounting hole" plane through (24, 0, 0) normal (1, 0, 0) x axis (0, 0, -1)
  circle C1 centre (-53.5, -54) radius 1.71
extrude "Extrude33" add sketch "Close former inner mounting hole" along normal blind 12
work_plane "WorkPlane34" AlongDistance 23.9 ExtraOffset 0
sketch "Matched outer mounting row" plane through (23.9, 0, 0) normal (1, 0, 0) x axis (0, 0, -1)
  circle C1 centre (-53.5, -70) radius 1.7
extrude "Extrude34" cut sketch "Matched outer mounting row" along normal blind 12.2
work_plane "WorkPlane42" AlongDistance 37.9 ExtraOffset 0
sketch "Restore separate cup guide bore" plane through (0, 0, 37.9) normal (0, 0, 1) x axis (1, 0, 0)
  circle C1 centre (5, -55) radius 1.7
work_plane "WorkPlane43" AlongDistance 37.9 ExtraOffset 0
sketch "Restore separate cup guide bore (1)" plane through (0, 0, 37.9) normal (0, 0, 1) x axis (1, 0, 0)
  circle C1 centre (19, -55) radius 1.7
extrude "Extrude43" cut sketch "Restore separate cup guide bore (1)" along normal blind 21.2
work_plane "WorkPlane44" AlongDistance -24.1 ExtraOffset 0
sketch "Preserve cam envelope" plane through (-24.1, 0, 0) normal (1, 0, 0) x axis (0, 0, -1)
  circle C1 centre (-65, 0) radius 51
work_plane "WorkPlane36" AlongDistance -55 ExtraOffset 0
sketch "Close inaccessible rail head pocket" plane through (0, -55, 0) normal (0, 1, 0) x axis (1, 0, 0)
  circle C1 centre (-30, -45) radius 5.31
extrude "Extrude36" add sketch "Close inaccessible rail head pocket" along normal blind 12
work_plane "WorkPlane37" AlongDistance 43 ExtraOffset 0
sketch "Close inaccessible rail head pocket (1)" plane through (0, 43, 0) normal (0, 1, 0) x axis (1, 0, 0)
  circle C1 centre (-30, -45) radius 5.31
extrude "Extrude37" add sketch "Close inaccessible rail head pocket (1)" along normal blind 12
work_plane "WorkPlane38" AlongDistance -75 ExtraOffset 0
sketch "Close obsolete side rail bore" plane through (0, -75, 0) normal (0, 1, 0) x axis (1, 0, 0)
  circle C1 centre (-30, -45) radius 2.71
extrude "Extrude38" add sketch "Close obsolete side rail bore" along normal blind 20
work_plane "WorkPlane39" AlongDistance 55 ExtraOffset 0
sketch "Close obsolete side rail bore (1)" plane through (0, 55, 0) normal (0, 1, 0) x axis (1, 0, 0)
  circle C1 centre (-30, -45) radius 2.71
extrude "Extrude39" add sketch "Close obsolete side rail bore (1)" along normal blind 20
work_plane "WorkPlane40" AlongDistance -36 ExtraOffset 0
sketch "Top-access 2020 mounting flange" plane through (-36, 0, 0) normal (1, 0, 0) x axis (0, 0, -1)
  line L1 (-55, -70) -> (-55, -95)
  line L2 (-63, -70) -> (-55, -70)
  line L3 (-63, -95) -> (-63, -70)
  line L4 (-55, -95) -> (-63, -95)
extrude "Extrude40" add sketch "Top-access 2020 mounting flange" along normal blind 12
work_plane "WorkPlane41" AlongDistance -36 ExtraOffset 0
sketch "Mount root triangular reinforcement" plane through (-36, 0, 0) normal (1, 0, 0) x axis (0, 0, -1)
  line L1 (-56, -63) -> (-56, -70)
  line L2 (-63, -70) -> (-56, -63)
  line L3 (-56, -70) -> (-63, -70)
extrude "Extrude41" add sketch "Mount root triangular reinforcement" along normal blind 12
work_plane "WorkPlane42" AlongDistance 54.9 ExtraOffset 0
sketch "Vertical M5 rail mounting bore" plane through (0, 0, 54.9) normal (0, 0, 1) x axis (1, 0, 0)
  circle C1 centre (-30, -85) radius 2.7
extrude "Extrude42" cut sketch "Vertical M5 rail mounting bore" along normal blind 8.2
work_plane "WorkPlane43" AlongDistance -36 ExtraOffset 0
sketch "Top-access 2020 mounting flange (1)" plane through (-36, 0, 0) normal (1, 0, 0) x axis (0, 0, -1)
  line L1 (-55, 95) -> (-55, 70)
  line L2 (-63, 95) -> (-55, 95)
  line L3 (-63, 70) -> (-63, 95)
  line L4 (-55, 70) -> (-63, 70)
extrude "Extrude43" add sketch "Top-access 2020 mounting flange (1)" along normal blind 12
work_plane "WorkPlane44" AlongDistance -36 ExtraOffset 0
sketch "Mount root triangular reinforcement (1)" plane through (-36, 0, 0) normal (1, 0, 0) x axis (0, 0, -1)
  line L1 (-56, 70) -> (-56, 63)
  line L2 (-63, 70) -> (-56, 70)
  line L3 (-56, 63) -> (-63, 70)
extrude "Extrude44" add sketch "Mount root triangular reinforcement (1)" along normal blind 12
work_plane "WorkPlane45" AlongDistance 54.9 ExtraOffset 0
sketch "Vertical M5 rail mounting bore (1)" plane through (0, 0, 54.9) normal (0, 0, 1) x axis (1, 0, 0)
  circle C1 centre (-30, 85) radius 2.7
extrude "Extrude45" cut sketch "Vertical M5 rail mounting bore (1)" along normal blind 8.2
work_plane "WorkPlane46" AlongDistance -36 ExtraOffset 0
sketch "Close old M5 pivot clearance" plane through (-36, 0, 0) normal (1, 0, 0) x axis (0, 0, -1)
  circle C1 centre (-12, -35) radius 2.71
extrude "Extrude46" add sketch "Close old M5 pivot clearance" along normal blind 12
work_plane "WorkPlane47" AlongDistance -36.1 ExtraOffset 0
sketch "M3 follower pivot clearance" plane through (-36.1, 0, 0) normal (1, 0, 0) x axis (0, 0, -1)
  circle C1 centre (-12, -35) radius 1.7
extrude "Extrude47" cut sketch "M3 follower pivot clearance" along normal blind 12.2
work_plane "WorkPlane35" AlongDistance -55 ExtraOffset 0
sketch "Close inaccessible rail head pocket" plane through (0, -55, 0) normal (0, 1, 0) x axis (1, 0, 0)
  circle C1 centre (30, -45) radius 5.31
extrude "Extrude35" add sketch "Close inaccessible rail head pocket" along normal blind 12
work_plane "WorkPlane36" AlongDistance 43 ExtraOffset 0
sketch "Close inaccessible rail head pocket (1)" plane through (0, 43, 0) normal (0, 1, 0) x axis (1, 0, 0)
  circle C1 centre (30, -45) radius 5.31
extrude "Extrude36" add sketch "Close inaccessible rail head pocket (1)" along normal blind 12
work_plane "WorkPlane37" AlongDistance -75 ExtraOffset 0
sketch "Close obsolete side rail bore" plane through (0, -75, 0) normal (0, 1, 0) x axis (1, 0, 0)
  circle C1 centre (30, -45) radius 2.71
extrude "Extrude37" add sketch "Close obsolete side rail bore" along normal blind 20
work_plane "WorkPlane38" AlongDistance 55 ExtraOffset 0
sketch "Close obsolete side rail bore (1)" plane through (0, 55, 0) normal (0, 1, 0) x axis (1, 0, 0)
  circle C1 centre (30, -45) radius 2.71
extrude "Extrude38" add sketch "Close obsolete side rail bore (1)" along normal blind 20
work_plane "WorkPlane39" AlongDistance 24 ExtraOffset 0
sketch "Top-access 2020 mounting flange" plane through (24, 0, 0) normal (1, 0, 0) x axis (0, 0, -1)
  line L1 (-55, -70) -> (-55, -95)
  line L2 (-63, -70) -> (-55, -70)
  line L3 (-63, -95) -> (-63, -70)
  line L4 (-55, -95) -> (-63, -95)
extrude "Extrude39" add sketch "Top-access 2020 mounting flange" along normal blind 12
work_plane "WorkPlane40" AlongDistance 24 ExtraOffset 0
sketch "Mount root triangular reinforcement" plane through (24, 0, 0) normal (1, 0, 0) x axis (0, 0, -1)
  line L1 (-56, -63) -> (-56, -70)
  line L2 (-63, -70) -> (-56, -63)
  line L3 (-56, -70) -> (-63, -70)
extrude "Extrude40" add sketch "Mount root triangular reinforcement" along normal blind 12
work_plane "WorkPlane41" AlongDistance 54.9 ExtraOffset 0
sketch "Vertical M5 rail mounting bore" plane through (0, 0, 54.9) normal (0, 0, 1) x axis (1, 0, 0)
  circle C1 centre (30, -85) radius 2.7
extrude "Extrude41" cut sketch "Vertical M5 rail mounting bore" along normal blind 8.2
work_plane "WorkPlane42" AlongDistance 24 ExtraOffset 0
sketch "Top-access 2020 mounting flange (1)" plane through (24, 0, 0) normal (1, 0, 0) x axis (0, 0, -1)
  line L1 (-55, 95) -> (-55, 70)
  line L2 (-63, 95) -> (-55, 95)
  line L3 (-63, 70) -> (-63, 95)
  line L4 (-55, 70) -> (-63, 70)
extrude "Extrude42" add sketch "Top-access 2020 mounting flange (1)" along normal blind 12
work_plane "WorkPlane43" AlongDistance 24 ExtraOffset 0
sketch "Mount root triangular reinforcement (1)" plane through (24, 0, 0) normal (1, 0, 0) x axis (0, 0, -1)
  line L1 (-56, 70) -> (-56, 63)
  line L2 (-63, 70) -> (-56, 70)
  line L3 (-56, 63) -> (-63, 70)
extrude "Extrude43" add sketch "Mount root triangular reinforcement (1)" along normal blind 12
work_plane "WorkPlane44" AlongDistance 54.9 ExtraOffset 0
sketch "Vertical M5 rail mounting bore (1)" plane through (0, 0, 54.9) normal (0, 0, 1) x axis (1, 0, 0)
  circle C1 centre (30, 85) radius 2.7
extrude "Extrude44" cut sketch "Vertical M5 rail mounting bore (1)" along normal blind 8.2
work_plane "WorkPlane45" AlongDistance 24 ExtraOffset 0
sketch "Close old M5 pivot clearance" plane through (24, 0, 0) normal (1, 0, 0) x axis (0, 0, -1)
  circle C1 centre (-12, -35) radius 2.71
extrude "Extrude45" add sketch "Close old M5 pivot clearance" along normal blind 12
work_plane "WorkPlane46" AlongDistance 23.9 ExtraOffset 0
sketch "M3 follower pivot clearance" plane through (23.9, 0, 0) normal (1, 0, 0) x axis (0, 0, -1)
  circle C1 centre (-12, -35) radius 1.7
extrude "Extrude46" cut sketch "M3 follower pivot clearance" along normal blind 12.2
work_plane "WorkPlane47" AlongDistance 23.9 ExtraOffset 0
